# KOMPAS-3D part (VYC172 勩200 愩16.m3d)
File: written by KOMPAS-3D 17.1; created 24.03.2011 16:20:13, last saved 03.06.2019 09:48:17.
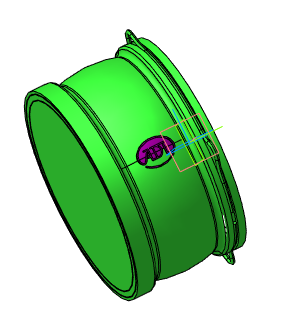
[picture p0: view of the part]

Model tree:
1. Операция без истории:2

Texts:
  Viktor2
